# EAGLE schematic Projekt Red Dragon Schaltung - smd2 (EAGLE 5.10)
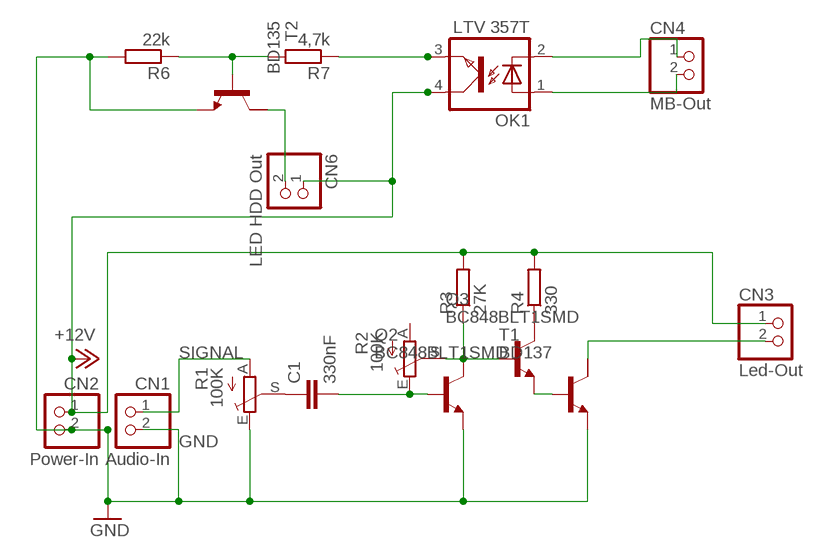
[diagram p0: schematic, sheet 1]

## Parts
C1  330nF  C-EU050-024X044  [C050-024X044]
CN1  Audio-In  PINHD-1X2  [1X02]
CN2  Power-In  PINHD-1X2  [1X02]
CN3  Led-Out  PINHD-1X2  [1X02]
CN4  MB-Out  PINHD-1X2  [1X02]
CN6  LED HDD Out  PINHD-1X2  [1X02]
OK1  LTV 357T  LTV816S  [SMD4]
Q2  BC848BLT1SMD  [SOT23]
Q3  BC848BLT1SMD  [SOT23]
R1  100K  TRIM_EU-S64W  [S64W]
R2  100K  TRIM_EU-S64W  [S64W]
R3  27K  R-EU_R1206  [R1206]
R4  330  R-EU_R1206  [R1206]
R6  22k  R-EU_R1206  [R1206]
R7  4,7k  R-EU_R1206  [R1206]
T1  BD137  -NPN-2C-BCE  [SOT89-BCE]
T2  BD135  -NPN-2C-BCE  [SOT89-BCE]

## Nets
+12V: CN2.1 CN3.1 CN6.1 OK1.4(COL) R3.2 R4.2
GND: CN1.2 CN2.2 Q2.2(E) R1.E R6.2 T1.E T2.E
N$1: C1.1 R1.S
N$2: C1.2 Q2.1(B) R2.E
N$3: Q2.3(C) Q3.1(B) R2.S R3.1
N$4: Q3.3(C) R4.1
N$5: Q3.2(E) T1.B
N$6: CN4.1 OK1.2(C)
N$7: R6.1 R7.2 T2.B
N$8: CN4.2 OK1.1(A)
N$9: CN3.2 T1.C
N$10: OK1.3(EMIT) R7.1
N$13: CN6.2 T2.C
SIGNAL: CN1.1 R1.A
Unconnected: R2.A T1.C@1(C) T2.C@1(C)

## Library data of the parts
C1 = rcl:C-EU: CAPACITOR, European symbol
CN1-CN4 CN6 = pinhead:PINHD-1X2: PIN HEADER
OK1 = optocoupler:LTV816: OPTO COUPLER Source: LITEON, LTV816.pdf
Q2 Q3 = transistor-npn:BC848*: NPN Transistor
R1 R2 = pot:TRIM_EU-: POTENTIOMETER
R3 R4 R6 R7 = rcl:R-EU_: RESISTOR, European symbol
T1 T2 = transistor:*-NPN-2C-: NPN Transistor with 2 Collector pins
